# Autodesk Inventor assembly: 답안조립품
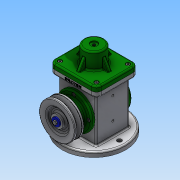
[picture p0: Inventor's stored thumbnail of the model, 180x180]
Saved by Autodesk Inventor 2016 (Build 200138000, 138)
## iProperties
Created: 2018-10
Part Number: 답안조립품
Material: 일반
Document SubType Name: Assembly
Designer: Administrator
Author: Administrator
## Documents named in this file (18)
- C:\Users\Administrator\Desktop\481007V1031\답안조립품.iam
- C:\Users\Administrator\Desktop\481007V1031\본체.ipt
- C:\Users\Administrator\Desktop\481007V1031\편심축.ipt
- C:\Users\Administrator\Desktop\481007V1031\링크.ipt
- C:\Users\Administrator\Desktop\481007V1031\슬라이더.ipt
- C:\Users\Administrator\Desktop\481007V1031\클레비스 핀 6 x 22.ipt
- 클레비스 핀 6 x 22.ipt
- C:\Users\Administrator\Desktop\481007V1031\덮개.ipt
- C:\Users\Administrator\Desktop\481007V1031\베어링 17 x 40 x 12.ipt
- C:\Users\Administrator\Desktop\481007V1031\뒤커버.ipt
- C:\Users\Administrator\Desktop\481007V1031\볼트 M4 x 8.ipt
- C:\Users\Administrator\Desktop\481007V1031\E-링.ipt
- C:\Users\Administrator\Desktop\481007V1031\앞커버.ipt
- C:\Users\Administrator\Desktop\481007V1031\오일 실 17 30 8.ipt
- C:\Users\Administrator\Desktop\481007V1031\키 4 x 4 x 12.ipt
- C:\Users\Administrator\Desktop\481007V1031\V-벨트풀리.ipt
- C:\Users\Administrator\Desktop\481007V1031\와셔 4x16.ipt
- C:\Users\Administrator\Desktop\481007V1031\볼트 M4 x 10.ipt
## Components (2 placed, 2 different names)
1. E-링:1
2. V-벨트풀리:1
